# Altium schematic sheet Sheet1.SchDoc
size 414 x 293 mm; SheetNumber: 1; SheetTotal: 1
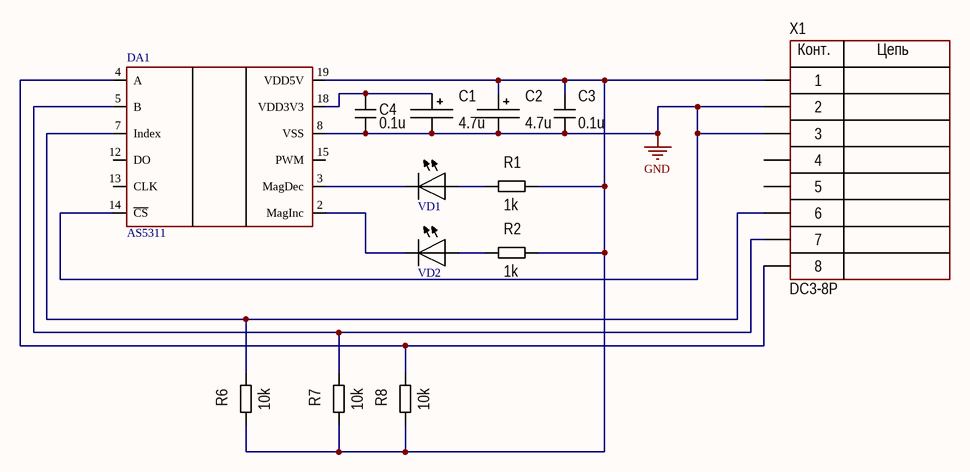
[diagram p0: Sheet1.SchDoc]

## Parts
C1  4.7u  [TANTAL_A]
C2  4.7u  [TANTAL_A]
C3  0.1u  [CH0603C]
C4  0.1u  [CH0805C]
DA1  AS5311  [20-TSSOP]
R1  1k  [CH0402R]
R2  1k  [CH0402R]
R6  10k  [CH0402R]
R7  10k  [CH0402R]
R8  10k  [CH0402R]
VD1  LED  [VD_0603]  (value not drawn)
VD2  LED  [VD_0603]  (value not drawn)
X1  DC3-8P  [CON: DC3 2x4P]

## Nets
GND: C1.2 C2.2 C3.1 C4.1 DA1.8(VSS) DA1.14(~{CS}) X1.2 X1.3
NetC1_1: C1.1 C4.2 DA1.18(VDD3V3)
NetC2_1: C2.1 C3.2 DA1.19(VDD5V) R1.2 R2.2 R6.1 R7.1 R8.1 X1.1
NetDA1_2: DA1.2(MagInc) VD2.2
NetDA1_3: DA1.3(MagDec) VD1.2
NetDA1_4: DA1.4(A) R8.2 X1.8
NetDA1_5: DA1.5(B) R7.2 X1.7
NetDA1_7: DA1.7(Index) R6.2 X1.6
NetR1_1: R1.1 VD1.1
NetR2_1: R2.1 VD2.1

Not connected (* = marked no-connect by the designer): DA1 12(DO) 13(CLK) 15(PWM); X1 4 5

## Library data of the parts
C1 C2 = TantalCap: Manufacturer: 10u; Model: TAJA475M010RNJ
C3 = Capacitor: Model: 06035C104JAT2A
C4 = Capacitor: Model: 08055C104JAT2A
DA1 = AS5311: Model: AS5311-ATST
R1 R2 = Resistor: Model: CR0402-JW-102GLF
R6-R8 = Resistor: Model: CR0402-JW-103GLF
VD1 = LED: Model: KPT-1608SGC
VD2 = LED: Model: KPT-1608YC
X1 = 8-Connector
